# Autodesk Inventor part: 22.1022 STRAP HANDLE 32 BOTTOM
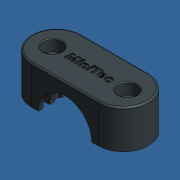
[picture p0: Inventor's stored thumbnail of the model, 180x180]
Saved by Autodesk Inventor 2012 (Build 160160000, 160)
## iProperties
Created: 2009-04
Part Number: 22.1022 STRAP HANDLE 32 BOTTOM
Document SubType Name: Modellieren
Designer: Pleli-Schmidt
Material: ABS Plastic
Mass: 20.7421 g
Surface Area: 138.98 cm^2
Volume: 19.5681 cm^3
Density: 1.06 g/cm^3
Description: Schelle 32 Einzelteil
Material: ABS Plastik
Bezeichnung: Schelle 32 Einzelteil
Artikelnr: 221022/1
Lieferantennr: 72401
Zeichnungsnr: 22-1022-1FZ.000
MiniTec_ID: 221022/1
Teileart: K
Lieferant: MiniTec
Title: Schelle 32 Einzelteil
Author: Pleli-Schmidt
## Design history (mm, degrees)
feature "Basis1"
body "Solid1"
